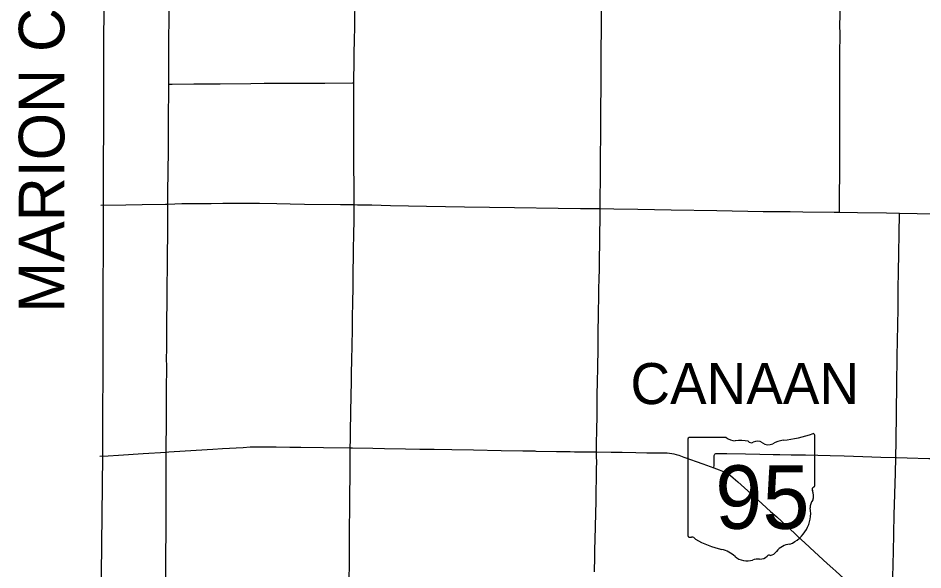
# Model space of a CAD drawing. Extents: x 9078 to 9739, y 4248 to 4966.
# Drawn here: x 9197.5 to 9296.8, y 4699.7 to 4760.2 of the extents above; entities that cross this region are included whole.
import ezdxf

# ---------------------------------------------------------------- set-up
doc = ezdxf.new("R2010")
doc.units = 0
for name, color, linetype in [('GM_X_Adjacent_County_Text', 7, 'Continuous'), ('GM_X_County', 7, 'Continuous'), ('GM_X_County_Road', 7, 'Continuous'), ('GM_X_State_Route', 7, 'Continuous'), ('GM_X_State_Shield', 7, 'Continuous'), ('GM_X_Township_Road', 7, 'Continuous'), ('GM_X_Township_Text', 7, 'Continuous')]:
    doc.layers.add(name, color=color, linetype=linetype)

msp = doc.modelspace()

# ---------------------------------------------------------------- linework, layer by layer
at = {"layer": 'GM_X_County'}
msp.add_lwpolyline([(9206.245, 4660.249), (9206.809, 4712.196), (9206.887, 4739.703), (9206.961, 4766.011), (9207.008, 4782.44), (9206.987, 4792.874), (9206.968, 4801.71), (9206.96, 4805.912), (9206.933, 4819.119), (9233.899, 4819.643), (9235.353, 4819.689), (9262.437, 4819.962), (9267.039, 4820.02), (9268.93, 4820.044), (9278.09, 4820.249), (9301.491, 4820.507)], dxfattribs=at)
at = {"layer": 'GM_X_County_Road'}
for points in [[(9261.375, 4739.312), (9261.377, 4739.518), (9261.383, 4740.831), (9261.394, 4742.225), (9261.402, 4742.963), (9261.412, 4744.194), (9261.418, 4745.588), (9261.425, 4746.819), (9261.437, 4748.213), (9261.443, 4749.28), (9261.447, 4750.592), (9261.459, 4752.396), (9261.467, 4753.053), (9261.472, 4754.939), (9261.477, 4756.498), (9261.482, 4757.318), (9261.496, 4758.384), (9261.508, 4759.779), (9261.518, 4761.173), (9261.517, 4762.568), (9261.542, 4765.275), (9261.534, 4765.997)], [(9287.625, 4738.92), (9287.624, 4739.144), (9287.623, 4739.882), (9287.641, 4744.068), (9287.647, 4746.612), (9287.653, 4750.633), (9287.653, 4752.356), (9287.649, 4753.587), (9287.646, 4754.407), (9287.665, 4756.294), (9287.676, 4758.428), (9287.668, 4759.494), (9287.676, 4760.479), (9287.676, 4763.105), (9287.684, 4764.992), (9287.676, 4765.616)], [(9260.969, 4712.604), (9260.969, 4713.273), (9260.978, 4713.847), (9260.989, 4714.667), (9261.008, 4715.569), (9261.019, 4715.979), (9261.03, 4717.127), (9261.048, 4718.85), (9261.07, 4720.326), (9261.094, 4721.803), (9261.13, 4724.017), (9261.145, 4724.919), (9261.155, 4726.15), (9261.182, 4727.219), (9261.196, 4728.125), (9261.211, 4729.43), (9261.23, 4730.742), (9261.242, 4731.399), (9261.275, 4732.875), (9261.342, 4736.44), (9261.363, 4738.288), (9261.375, 4739.312)], [(9261.375, 4739.312), (9262.857, 4739.294), (9265.48, 4739.243), (9269.171, 4739.181), (9274.173, 4739.097), (9279.257, 4739.005), (9282.209, 4738.977), (9283.603, 4738.968), (9287.049, 4738.929), (9287.625, 4738.92)], [(9287.625, 4738.92), (9289.591, 4738.89), (9292.789, 4738.841), (9294.186, 4738.812)], [(9294.186, 4738.812), (9300.005, 4738.697), (9302.712, 4738.647), (9307.276, 4738.54)], [(9233.72, 4686.447), (9233.727, 4686.932), (9233.743, 4688.162), (9233.753, 4689.393), (9233.775, 4692.591), (9233.794, 4694.395), (9233.818, 4696.856), (9233.829, 4698.25), (9233.845, 4699.152), (9233.856, 4699.726), (9233.857, 4700.71), (9233.861, 4702.35), (9233.878, 4703.826), (9233.886, 4704.892), (9233.894, 4705.712), (9233.899, 4707.024), (9233.911, 4708.172), (9233.927, 4709.73), (9233.933, 4710.632), (9233.941, 4711.698), (9233.948, 4713.054)], [(9260.755, 4699.443), (9260.785, 4701.084), (9260.792, 4701.575), (9260.797, 4701.979), (9260.814, 4702.887), (9260.854, 4704.527), (9260.875, 4705.757), (9260.909, 4707.315), (9260.931, 4708.463), (9260.955, 4709.533), (9260.959, 4709.797), (9260.967, 4710.008), (9260.969, 4710.166), (9260.975, 4710.409), (9260.977, 4710.735), (9260.981, 4710.98), (9260.984, 4711.308), (9260.982, 4711.636), (9260.979, 4711.971), (9260.969, 4712.535), (9260.969, 4712.604)], [(9273.845, 4710.863), (9273.847, 4710.897), (9273.858, 4711.108), (9273.864, 4711.226), (9273.868, 4711.392), (9273.863, 4711.884), (9273.864, 4712.129), (9273.872, 4712.209), (9273.891, 4712.283), (9273.926, 4712.348), (9273.98, 4712.397), (9274.048, 4712.43), (9274.123, 4712.445), (9274.203, 4712.451), (9274.284, 4712.452), (9274.611, 4712.44), (9275.267, 4712.423), (9277.317, 4712.396), (9278.874, 4712.359), (9280.351, 4712.336), (9281.088, 4712.32), (9282.318, 4712.307), (9283.876, 4712.273), (9286.581, 4712.219), (9288.138, 4712.168), (9290.187, 4712.093), (9292.154, 4712.024), (9293.779, 4711.983)], [(9293.779, 4711.983), (9293.876, 4711.98), (9295.023, 4711.955), (9297.401, 4711.905), (9298.795, 4711.881), (9299.86, 4711.854), (9301.336, 4711.832), (9302.812, 4711.806), (9303.947, 4711.793)]]:
    msp.add_lwpolyline(points, dxfattribs=at)
at = {"layer": 'GM_X_State_Route'}
for points in [[(9206.489, 4712.147), (9207.403, 4712.196), (9208.549, 4712.259), (9211.251, 4712.428), (9213.776, 4712.594), (9214.035, 4712.611), (9217.064, 4712.803), (9218.865, 4712.91), (9219.93, 4712.974), (9222.222, 4713.108), (9222.96, 4713.149), (9223.616, 4713.172), (9224.519, 4713.175), (9225.832, 4713.158), (9227.308, 4713.132), (9228.539, 4713.118), (9231, 4713.085), (9233.948, 4713.054), (9234.199, 4713.051), (9236.414, 4713.02), (9237.726, 4712.989), (9240.023, 4712.953), (9241.581, 4712.923), (9243.139, 4712.899), (9245.108, 4712.861), (9247.486, 4712.826), (9250.521, 4712.773), (9252.9, 4712.727), (9254.212, 4712.71), (9254.319, 4712.708)], [(9254.319, 4712.708), (9256.591, 4712.666), (9258.067, 4712.643), (9258.567, 4712.635)], [(9258.567, 4712.635), (9259.461, 4712.621), (9260.938, 4712.604), (9260.969, 4712.604), (9262.577, 4712.584), (9262.746, 4712.584), (9262.899, 4712.579), (9263.223, 4712.57), (9263.795, 4712.565), (9265.272, 4712.542), (9266.502, 4712.527), (9268.307, 4712.506), (9268.718, 4712.494), (9268.965, 4712.475), (9269.21, 4712.441), (9269.453, 4712.394), (9269.692, 4712.332), (9270.007, 4712.236), (9270.549, 4712.045), (9272.634, 4711.296), (9273.845, 4710.863), (9274.41, 4710.659), (9274.794, 4710.513), (9275.021, 4710.413), (9275.239, 4710.296), (9275.448, 4710.162), (9275.647, 4710.015), (9275.966, 4709.756), (9276.46, 4709.322), (9277.554, 4708.331), (9278.29, 4707.677), (9279.143, 4706.909), (9280.059, 4706.087), (9280.726, 4705.479), (9281.759, 4704.542), (9282.666, 4703.709), (9283.058, 4703.341)], [(9283.058, 4703.341), (9283.803, 4702.644), (9284.888, 4701.642), (9286.274, 4700.363), (9286.88, 4699.81), (9287.207, 4699.513), (9288.083, 4698.718), (9288.824, 4698.046), (9290.407, 4696.617), (9291.872, 4695.301), (9293.04, 4694.242)]]:
    msp.add_lwpolyline(points, dxfattribs=at)
at = {"layer": 'GM_X_State_Shield'}
for p, q in [((9284.897, 4708.91), (9284.897, 4714.437)), ((9270.975, 4713.994), (9270.975, 4703.427)), ((9275.19, 4714.176), (9271.112, 4714.176)), ((9284.896, 4708.911), (9284.897, 4708.91))]:
    msp.add_line(p, q, dxfattribs=at)
for centre, radius, start, end in [((9279.938, 4728.581), 14.764, 275.84447, 288.90645), ((9284.743, 4714.46), 0.155, 351.86209, 97.738), ((9271.135, 4714.016), 0.161, 98.1301, 188.1301), ((9276.16, 4715.402), 1.564, 231.61951, 271.11188), ((9276.679, 4708.243), 5.616, 80.48669, 94.98827), ((9277.954, 4714.071), 0.451, 219.79206, 297.10237), ((9278.617, 4712.85), 0.938, 54.46668, 119.14113), ((9279.828, 4714.525), 1.129, 233.85621, 294.82819), ((9281.821, 4710.948), 2.97, 97.34618, 120.76885), ((9284.861, 4708.504), 0.24, 107.94398, 210.33697), ((9283.335, 4707.806), 1.44, 340.03296, 23.64957), ((9284.732, 4708.889), 0.166, 289.60381, 7.73413), ((9285.452, 4706.597), 1.048, 136.8065, 186.92959), ((9280.765, 4705.894), 3.693, 292.30889, 8.98584), ((9271.136, 4703.404), 0.163, 171.95839, 258.30661), ((9271.161, 4704.485), 1.242, 267.33899, 280.60386), ((9271.415, 4702.818), 0.448, 29.74838, 93.27175), ((9277.068, 4712.311), 10.661, 240.41292, 257.1985), ((9282.322, 4700.461), 2.022, 94.40312, 142.57675), ((9273.889, 4698.68), 3.336, 47.18416, 75.83597), ((9279.76, 4702.403), 1.193, 282.87319, 323.27711), ((9277.497, 4702.765), 2.117, 230.70037, 286.29184), ((9278.72, 4699.112), 1.739, 85.69512, 111.20995), ((9278.875, 4701.974), 1.128, 268.77702, 315.54927), ((9279.895, 4700.951), 0.318, 65.75173, 132.64842)]:
    msp.add_arc(centre, radius, start, end, dxfattribs=at)
at = {"layer": 'GM_X_Township_Road'}
for points in [[(9214.042, 4752.966), (9214.046, 4754.006), (9214.053, 4755.647), (9214.063, 4756.877), (9214.07, 4757.944), (9214.081, 4760.076), (9214.088, 4761.307), (9214.102, 4762.865), (9214.115, 4764.752), (9214.115, 4766.065), (9214.117, 4766.345)], [(9234.354, 4753.115), (9234.359, 4753.845), (9234.37, 4754.912), (9234.396, 4756.553), (9234.408, 4757.62), (9234.441, 4759.426), (9234.481, 4762.545), (9234.513, 4764.515), (9234.547, 4766.238), (9234.551, 4766.426)], [(9213.956, 4739.81), (9213.955, 4740.39), (9213.953, 4741.046), (9213.96, 4741.784), (9213.973, 4742.686), (9213.991, 4743.999), (9214.001, 4745.065), (9214.013, 4746.541), (9214.02, 4747.608), (9214.025, 4748.592), (9214.033, 4750.069), (9214.039, 4751.627), (9214.041, 4752.53), (9214.042, 4752.966)], [(9214.042, 4752.966), (9214.144, 4752.967), (9214.428, 4752.968), (9216.811, 4752.995), (9219.687, 4753.013), (9223.055, 4753.042), (9224.526, 4753.065), (9225.836, 4753.058), (9226.57, 4753.063), (9227.963, 4753.087), (9229.199, 4753.073), (9231.171, 4753.084), (9234.212, 4753.113), (9234.354, 4753.115)], [(9234.379, 4739.747), (9234.38, 4740.142), (9234.368, 4741.947), (9234.352, 4743.835), (9234.347, 4747.693), (9234.346, 4749.006), (9234.332, 4749.991), (9234.342, 4750.564), (9234.342, 4751.057), (9234.335, 4751.385), (9234.332, 4752.041), (9234.354, 4753.025), (9234.354, 4753.115)], [(9206.608, 4739.682), (9209.334, 4739.706), (9211.139, 4739.747), (9213.681, 4739.802), (9213.956, 4739.81)], [(9213.822, 4725.383), (9213.822, 4725.546), (9213.833, 4726.53), (9213.838, 4726.942), (9213.846, 4727.594), (9213.857, 4728.496), (9213.87, 4729.809), (9213.882, 4730.957), (9213.892, 4732.762), (9213.904, 4733.417), (9213.919, 4734.238), (9213.939, 4736.534), (9213.944, 4738.011), (9213.952, 4738.831), (9213.956, 4739.651), (9213.956, 4739.81)], [(9213.956, 4739.81), (9215.485, 4739.852), (9218.685, 4739.884), (9219.972, 4739.905)], [(9219.972, 4739.905), (9220.566, 4739.915), (9221.633, 4739.914), (9224.012, 4739.889), (9225.898, 4739.855), (9227.375, 4739.838), (9228.933, 4739.814), (9232.871, 4739.77), (9234.379, 4739.747)], [(9233.948, 4713.054), (9233.952, 4713.224), (9233.966, 4713.798), (9233.99, 4715.029), (9234.028, 4716.752), (9234.066, 4718.968), (9234.086, 4720.117), (9234.103, 4721.43), (9234.124, 4722.497), (9234.17, 4724.466), (9234.195, 4725.862), (9234.214, 4727.175), (9234.244, 4729.226), (9234.249, 4729.637), (9234.254, 4730.047), (9234.275, 4731.853), (9234.289, 4732.755), (9234.306, 4733.74), (9234.326, 4734.889), (9234.345, 4736.449), (9234.37, 4738.09), (9234.379, 4738.828), (9234.379, 4739.747)], [(9234.379, 4739.747), (9234.757, 4739.74), (9236.316, 4739.717), (9238.366, 4739.668), (9242.303, 4739.584), (9246.487, 4739.505), (9251.982, 4739.424), (9256.74, 4739.358), (9259.2, 4739.322), (9261.298, 4739.312), (9261.375, 4739.312)], [(9293.779, 4711.983), (9293.816, 4713.801), (9293.906, 4720.028), (9293.953, 4722.978), (9293.984, 4724.945), (9294.01, 4726.42), (9294.037, 4728.468), (9294.069, 4730.353), (9294.099, 4732.566), (9294.121, 4734.204), (9294.164, 4736.745), (9294.184, 4738.547), (9294.186, 4738.812)], [(9213.776, 4712.594), (9213.777, 4712.75), (9213.778, 4713.652), (9213.784, 4715.128), (9213.794, 4716.277), (9213.815, 4719.394), (9213.816, 4722.019), (9213.808, 4722.839), (9213.817, 4723.905), (9213.822, 4725.383)], [(9213.652, 4686.639), (9213.654, 4687.484), (9213.662, 4689.535), (9213.674, 4690.765), (9213.693, 4692.98), (9213.699, 4694.375), (9213.706, 4695.359), (9213.715, 4696.261), (9213.726, 4697.984), (9213.742, 4700.035), (9213.742, 4701.347), (9213.751, 4703.808), (9213.756, 4705.367), (9213.76, 4706.515), (9213.768, 4709.14), (9213.776, 4711.437), (9213.775, 4712.258), (9213.776, 4712.594)], [(9293.471, 4698.744), (9293.501, 4700.364), (9293.527, 4701.593), (9293.629, 4705.689), (9293.745, 4710.277), (9293.779, 4711.983)]]:
    msp.add_lwpolyline(points, dxfattribs=at)

# ---------------------------------------------------------------- texts
at = {"layer": 'GM_X_Adjacent_County_Text'}
msp.add_text('MARION COUNTY', height=5, rotation=90, dxfattribs=at).set_placement((9202.594, 4727.893))
at = {"layer": 'GM_X_State_Shield'}
msp.add_text('95', height=6.961, dxfattribs=at).set_placement((9273.979, 4704.172))
at = {"layer": 'GM_X_Township_Text'}
msp.add_text('CANAAN', height=4.5, rotation=0.00001, dxfattribs=at).set_placement((9264.686, 4717.857))

doc.saveas('drawing.dxf')
